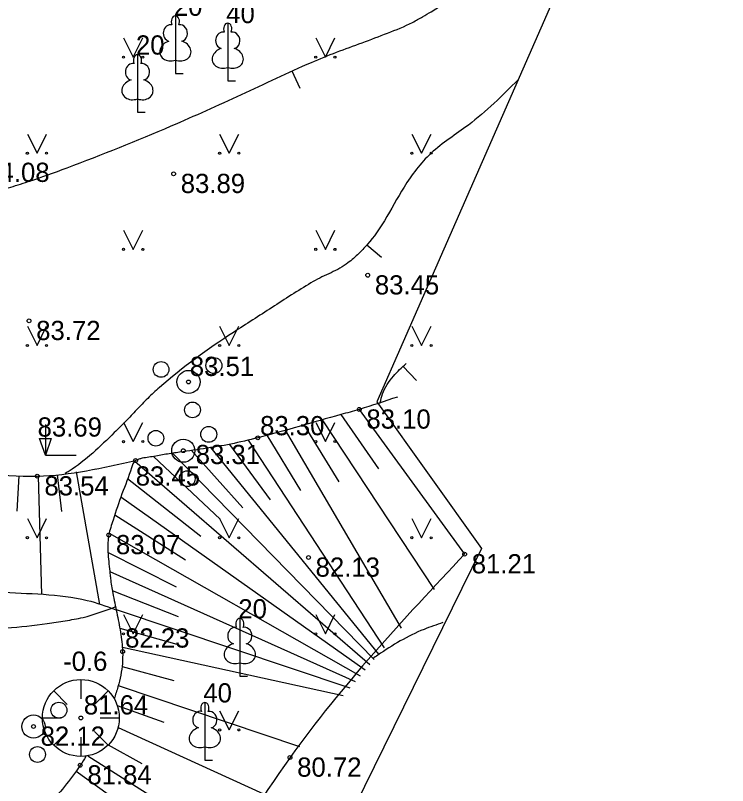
# Model space of a CAD drawing. Extents: x 576692 to 577659, y 273254 to 273799.
# Drawn here: x 577554.44 to 577572.96, y 273358.55 to 273378.59 of the extents above; entities that cross this region are included whole.
import ezdxf

# ---------------------------------------------------------------- set-up
doc = ezdxf.new("R2010")
doc.units = 0
for name, color, linetype in [('APGR_SARK_####_####_#', 7, 'Continuous'), ('CELI_TAKA_####_####_#', 7, 'Continuous'), ('GAZE_ELEM_####_####_#', 7, 'Continuous'), ('GEOD_ELEM_####_TKST_#', 7, 'Continuous'), ('GEOD_SITP_####_TKST_#', 7, 'Continuous'), ('HIDT_REZV_####_TKST_#', 7, 'Continuous'), ('LKAN_ELEM_PAST_TKST_#', 7, 'Continuous'), ('LKAN_VADP_PAST_####_#', 7, 'Continuous'), ('RELJ_ELEM_####_####_#', 7, 'Continuous'), ('SAKT_ELEM_####_####_#', 7, 'Continuous')]:
    doc.layers.add(name, color=color, linetype=linetype)

msp = doc.modelspace()

# ---------------------------------------------------------------- linework, layer by layer
at = {"layer": 'CELI_TAKA_####_####_#'}
msp.add_lwpolyline([(577600.316, 273457.536), (577582.857, 273411.886), (577563.839, 273368.538), (577566.562, 273364.718), (577549.809, 273330.664), (577542.026, 273316.827), (577531.9, 273318.477), (577518.827, 273308.06), (577506.987, 273310.355), (577491.731, 273322.549), (577476.131, 273318.008), (577456.124, 273316.473), (577442.567, 273287.391)], dxfattribs=at)
at = {"layer": 'GAZE_ELEM_####_####_#'}
for p, q in [((577563.382, 273368.337), (577566.122, 273364.573)), ((577562.9, 273368.202), (577563.886, 273366.793)), ((577561.937, 273367.933), (577562.854, 273366.453)), ((577562.419, 273368.068), (577565.329, 273363.649)), ((577561.456, 273367.799), (577564.468, 273362.647)), ((577560.492, 273367.534), (577564.026, 273362.132)), ((577560.974, 273367.664), (577561.855, 273366.225)), ((577559.51, 273367.343), (577563.886, 273361.968)), ((577560.003, 273367.428), (577561.062, 273365.985)), ((577558.521, 273367.195), (577563.767, 273361.83)), ((577559.016, 273367.268), (577560.354, 273365.774)), ((577557.493, 273366.996), (577557.493, 273366.996)), ((577557.546, 273366.995), (577563.66, 273361.705)), ((577558.028, 273367.114), (577559.76, 273365.485)), ((577556.511, 273366.804), (577556.511, 273366.804)), ((577557.001, 273366.904), (577557.001, 273366.904)), ((577554.528, 273366.611), (577554.472, 273365.694)), ((577555.027, 273366.601), (577555.115, 273363.521)), ((577555.526, 273366.637), (577555.639, 273365.685)), ((577556.02, 273366.71), (577556.627, 273363.267)), ((577557.353, 273366.538), (577559.263, 273365.038)), ((577557.184, 273366.067), (577563.536, 273361.561)), ((577557.023, 273365.594), (577558.859, 273364.424)), ((577556.877, 273365.116), (577563.404, 273361.407)), ((577558.63, 273363.716), (577556.846, 273364.619)), ((577556.893, 273364.121), (577563.275, 273361.257)), ((577556.959, 273363.625), (577558.673, 273362.954)), ((577557.056, 273363.135), (577563.134, 273361.093)), ((577557.153, 273362.645), (577558.64, 273362.23)), ((577557.22, 273362.149), (577562.963, 273360.893)), ((577557.212, 273361.65), (577558.559, 273361.287)), ((577557.115, 273361.16), (577561.825, 273359.568)), ((577557.086, 273360.64), (577558.297, 273360.201)), ((577557.111, 273360.068), (577560.895, 273358.341)), ((577556.853, 273359.609), (577557.73, 273359.13)), ((577556.321, 273359.328), (577560.103, 273356.941)), ((577556.017, 273358.93), (577557.132, 273358.13))]:
    msp.add_line(p, q, dxfattribs=at)
for points in [[(577556.274, 273359.307), (577556.124, 273359.082), (577555.713, 273358.527), (577555.271, 273358.028), (577554.768, 273357.574), (577554.485, 273357.361), (577554.334, 273357.257), (577554.176, 273357.155), (577554.073, 273357.1), (577553.967, 273357.063), (577553.861, 273357.047), (577553.757, 273357.054), (577553.172, 273357.221), (577552.593, 273357.48), (577552.308, 273357.66), (577552.157, 273357.847), (577552.118, 273357.98), (577552.083, 273358.112), (577552.023, 273358.376), (577551.94, 273358.907), (577551.893, 273359.44), (577551.866, 273359.976), (577551.783, 273362.009), (577551.767, 273363.023), (577551.775, 273363.531), (577551.794, 273364.038), (577551.842, 273364.628), (577551.911, 273365.218), (577551.985, 273365.808), (577552.044, 273366.397), (577552.052, 273366.952), (577552.016, 273367.194), (577551.954, 273367.432), (577551.775, 273367.893), (577551.652, 273368.142), (577551.524, 273368.386), (577551.279, 273368.88), (577550.489, 273370.674), (577550.237, 273371.247), (577549.35, 273372.831), (577548.462, 273374.158)], [(577564.374, 273368.659), (577563.382, 273368.337), (577562.9, 273368.202), (577560.742, 273367.599), (577560.042, 273367.436), (577559.333, 273367.315), (577558.62, 273367.21), (577558.264, 273367.155), (577557.909, 273367.093), (577557.735, 273367.066), (577557.649, 273367.044), (577557.607, 273367.029), (577557.565, 273367.008), (577557.494, 273366.924), (577557.456, 273366.817), (577557.21, 273366.14), (577556.978, 273365.457), (577556.868, 273365.071), (577556.851, 273364.947), (577556.843, 273364.821), (577556.849, 273364.569), (577556.898, 273364.066), (577556.912, 273363.939), (577556.971, 273363.558), (577557.074, 273363.051), (577557.171, 273362.544), (577557.206, 273362.29), (577557.227, 273362.037), (577557.177, 273361.425), (577557.104, 273361.12), (577557.009, 273360.815)], [(577552.052, 273366.952), (577555.007, 273366.6), (577557.565, 273367.008)]]:
    msp.add_spline(points, degree=3, dxfattribs=at)
at = {"layer": 'GEOD_ELEM_####_TKST_#'}
msp.add_line((577561.847, 273376.684), (577561.641, 273377.139), dxfattribs=at)
msp.add_spline([(577552.135, 273373.738), (577552.569, 273373.777), (577553.728, 273373.95), (577554.251, 273374.099), (577554.767, 273374.261), (577555.784, 273374.622), (577558.491, 273375.711), (577559.408, 273376.113), (577560.319, 273376.53), (577561.227, 273376.95), (577562.139, 273377.363), (577562.794, 273377.63), (577563.457, 273377.875), (577564.119, 273378.125), (577564.769, 273378.405), (577565.029, 273378.55), (577565.252, 273378.682), (577565.57, 273378.894), (577565.767, 273379.042), (577565.833, 273379.094), (577565.934, 273379.188), (577566.124, 273379.412), (577566.454, 273379.912), (577566.84, 273380.678), (577567.333, 273381.728), (577567.755, 273382.508)], degree=3, dxfattribs=at)
at = {"layer": 'GEOD_SITP_####_TKST_#'}
for p, q in [((577563.959, 273372.285), (577563.577, 273372.608)), ((577564.873, 273369.093), (577564.523, 273369.45))]:
    msp.add_line(p, q, dxfattribs=at)
for points in [[(577567.517, 273376.913), (577566.219, 273375.733), (577565.25, 273375), (577564.547, 273374.12), (577564.038, 273373.246), (577563.599, 273372.634), (577563.338, 273372.361), (577563.045, 273372.118), (577562.823, 273371.98), (577562.589, 273371.865), (577562.353, 273371.754), (577562.126, 273371.628), (577561.114, 273370.989), (577560.107, 273370.339), (577558.185, 273368.906), (577557.88, 273368.624), (577557.591, 273368.327), (577557.305, 273368.027), (577557.011, 273367.734), (577555.838, 273366.733), (577555.736, 273366.67)], [(577563.928, 273368.515), (577563.986, 273368.74), (577564.269, 273369.202), (577564.604, 273369.53)], [(577551.773, 273362.801), (577551.816, 273362.78), (577552.477, 273362.62), (577553.145, 273362.622), (577553.675, 273362.634), (577554.206, 273362.658), (577555.266, 273362.767), (577555.734, 273362.84), (577556.198, 273362.928), (577557.034, 273363.201)], [(577565.554, 273362.793), (577565.066, 273362.616), (577563.867, 273361.947), (577563.731, 273361.852)]]:
    msp.add_spline(points, degree=3, dxfattribs=at)
at = {"layer": 'LKAN_ELEM_PAST_TKST_#'}
for p, q in [((577557.25, 273378), (577557.5, 273377.5)), ((577557.5, 273377.5), (577557.75, 273378)), ((577562.25, 273378), (577562.5, 273377.5)), ((577562.5, 273377.5), (577562.75, 273378)), ((577558.599, 273377.421), (577558.599, 273377.074)), ((577559.961, 273377.231), (577559.961, 273376.884)), ((577558.599, 273377.074), (577558.799, 273377.074)), ((577559.961, 273376.884), (577560.161, 273376.884)), ((577557.613, 273376.413), (577557.613, 273376.066)), ((577557.613, 273376.066), (577557.813, 273376.066)), ((577554.75, 273375.5), (577555, 273375)), ((577555, 273375), (577555.25, 273375.5)), ((577559.75, 273375.5), (577560, 273375)), ((577560, 273375), (577560.25, 273375.5)), ((577564.75, 273375.5), (577565, 273375)), ((577565, 273375), (577565.25, 273375.5)), ((577557.25, 273373), (577557.5, 273372.5)), ((577557.5, 273372.5), (577557.75, 273373)), ((577562.25, 273373), (577562.5, 273372.5)), ((577562.5, 273372.5), (577562.75, 273373)), ((577554.75, 273370.5), (577555, 273370)), ((577555, 273370), (577555.25, 273370.5)), ((577559.75, 273370.5), (577560, 273370)), ((577560, 273370), (577560.25, 273370.5)), ((577564.75, 273370.5), (577565, 273370)), ((577565, 273370), (577565.25, 273370.5)), ((577555.217, 273367.948), (577555.217, 273367.148)), ((577557.25, 273368), (577557.5, 273367.5)), ((577557.5, 273367.5), (577557.75, 273368)), ((577562.25, 273368), (577562.5, 273367.5)), ((577562.5, 273367.5), (577562.75, 273368)), ((577555.217, 273367.148), (577556.017, 273367.148)), ((577554.75, 273365.5), (577555, 273365)), ((577555, 273365), (577555.25, 273365.5)), ((577559.75, 273365.5), (577560, 273365)), ((577560, 273365), (577560.25, 273365.5)), ((577564.75, 273365.5), (577565, 273365)), ((577565, 273365), (577565.25, 273365.5)), ((577557.25, 273363), (577557.5, 273362.5)), ((577557.5, 273362.5), (577557.75, 273363)), ((577562.25, 273363), (577562.5, 273362.5)), ((577562.5, 273362.5), (577562.75, 273363)), ((577560.275, 273361.748), (577560.275, 273361.401)), ((577560.275, 273361.401), (577560.475, 273361.401)), ((577559.75, 273360.5), (577560, 273360)), ((577560, 273360), (577560.25, 273360.5)), ((577559.365, 273359.562), (577559.365, 273359.215)), ((577559.365, 273359.215), (577559.565, 273359.215))]:
    msp.add_line(p, q, dxfattribs=at)
for points in [[(577558.599, 273378.574), (577558.599, 273377.421)], [(577559.961, 273378.384), (577559.961, 273377.231)], [(577558.689, 273378.342), (577558.688, 273378.343)], [(577560.051, 273378.152), (577560.05, 273378.153)], [(577557.613, 273377.566), (577557.613, 273376.413)], [(577557.703, 273377.334), (577557.702, 273377.335)], [(577560.275, 273362.901), (577560.275, 273361.748)], [(577560.365, 273362.669), (577560.364, 273362.67)], [(577559.365, 273360.715), (577559.365, 273359.562)], [(577559.455, 273360.483), (577559.454, 273360.484)]]:
    msp.add_lwpolyline(points, dxfattribs=at)
for centre, radius in [((577557.25, 273377.5), 0.028), ((577557.75, 273377.5), 0.0263), ((577562.25, 273377.5), 0.028), ((577562.75, 273377.5), 0.0263), ((577554.75, 273375), 0.028), ((577555.25, 273375), 0.0263), ((577559.75, 273375), 0.028), ((577560.25, 273375), 0.0263), ((577564.75, 273375), 0.028), ((577565.25, 273375), 0.0263), ((577557.25, 273372.5), 0.028), ((577557.75, 273372.5), 0.0263), ((577562.25, 273372.5), 0.028), ((577562.75, 273372.5), 0.0263), ((577554.75, 273370), 0.028), ((577555.25, 273370), 0.0263), ((577559.75, 273370), 0.028), ((577560.25, 273370), 0.0263), ((577564.75, 273370), 0.028), ((577565.25, 273370), 0.0263), ((577558.227, 273369.376), 0.204), ((577559.602, 273369.477), 0.207), ((577558.941, 273369.052), 0.301), ((577559.044, 273368.324), 0.205), ((577558.091, 273367.587), 0.204), ((577559.466, 273367.688), 0.207), ((577558.805, 273367.263), 0.301), ((577557.25, 273367.5), 0.028), ((577557.75, 273367.5), 0.0263), ((577562.25, 273367.5), 0.028), ((577562.75, 273367.5), 0.0263), ((577558.908, 273366.535), 0.205), ((577554.75, 273365), 0.028), ((577555.25, 273365), 0.0263), ((577559.75, 273365), 0.028), ((577560.25, 273365), 0.0263), ((577564.75, 273365), 0.028), ((577565.25, 273365), 0.0263), ((577557.25, 273362.5), 0.028), ((577557.75, 273362.5), 0.0263), ((577562.25, 273362.5), 0.028), ((577562.75, 273362.5), 0.0263), ((577555.57, 273360.514), 0.207), ((577554.909, 273360.089), 0.301), ((577559.75, 273360), 0.028), ((577560.25, 273360), 0.0263), ((577555.012, 273359.361), 0.205)]:
    msp.add_circle(centre, radius, dxfattribs=at)
for centre, major_axis, ratio, start_param, end_param in [((577558.599, 273378.424), (0, -0.15), 0.707107, 3.14537, 5.287485), ((577558.599, 273378.424), (0, -0.15), 0.707107, 0.995701, 3.137816), ((577558.471, 273378.129), (-0.039, -0.212), 0.861323, 3.141593, 6.283185), ((577558.727, 273378.129), (0.039, -0.212), 0.861323, 0, 3.141593), ((577559.961, 273378.234), (0, -0.15), 0.707107, 3.14537, 5.287485), ((577559.961, 273378.234), (0, -0.15), 0.707107, 0.995701, 3.137816), ((577559.833, 273377.939), (-0.039, -0.212), 0.861323, 3.141593, 6.283185), ((577560.089, 273377.939), (0.039, -0.212), 0.861323, 0, 3.141593), ((577558.509, 273377.667), (0.307, 0.095), 0.814445, 1.570796, 4.752015), ((577558.689, 273377.667), (-0.307, 0.095), 0.814445, 1.531171, 4.712389), ((577557.613, 273377.416), (0, -0.15), 0.707107, 3.14537, 5.287485), ((577557.613, 273377.416), (0, -0.15), 0.707107, 0.995701, 3.137816), ((577559.871, 273377.477), (0.307, 0.095), 0.814445, 1.570796, 4.752015), ((577560.051, 273377.477), (-0.307, 0.095), 0.814445, 1.531171, 4.712389), ((577557.485, 273377.121), (-0.039, -0.212), 0.861323, 3.141593, 6.283185), ((577557.741, 273377.121), (0.039, -0.212), 0.861323, 0, 3.141593), ((577557.523, 273376.659), (0.307, 0.095), 0.814445, 1.570796, 4.752015), ((577557.703, 273376.659), (-0.307, 0.095), 0.814445, 1.531171, 4.712389), ((577560.275, 273362.751), (0, -0.15), 0.707107, 3.14537, 5.287485), ((577560.275, 273362.751), (0, -0.15), 0.707107, 0.995701, 3.137816), ((577560.147, 273362.456), (-0.039, -0.212), 0.861323, 3.141593, 6.283185), ((577560.403, 273362.456), (0.039, -0.212), 0.861323, 0, 3.141593), ((577560.185, 273361.994), (0.307, 0.095), 0.814445, 1.570796, 4.752015), ((577560.365, 273361.994), (-0.307, 0.095), 0.814445, 1.531171, 4.712389), ((577559.365, 273360.565), (0, -0.15), 0.707107, 3.14537, 5.287485), ((577559.365, 273360.565), (0, -0.15), 0.707107, 0.995701, 3.137816), ((577559.237, 273360.27), (-0.039, -0.212), 0.861323, 3.141593, 6.283185), ((577559.493, 273360.27), (0.039, -0.212), 0.861323, 0, 3.141593), ((577559.275, 273359.808), (0.307, 0.095), 0.814445, 1.570796, 4.752015), ((577559.455, 273359.808), (-0.307, 0.095), 0.814445, 1.531171, 4.712389)]:
    msp.add_ellipse(centre, major_axis=major_axis, ratio=ratio, start_param=start_param, end_param=end_param, dxfattribs=at)
at = {"layer": 'RELJ_ELEM_####_####_#'}
for p, q in [((577556.141, 273361.312), (577556.141, 273360.812)), ((577555.434, 273361.019), (577555.788, 273360.665)), ((577556.495, 273360.665), (577556.848, 273361.019)), ((577555.141, 273360.312), (577555.641, 273360.312)), ((577556.641, 273360.312), (577557.141, 273360.312)), ((577555.434, 273359.605), (577555.788, 273359.958)), ((577556.495, 273359.958), (577556.848, 273359.605)), ((577556.141, 273359.812), (577556.141, 273359.312))]:
    msp.add_line(p, q, dxfattribs=at)
msp.add_lwpolyline([(577555.067, 273367.581), (577555.367, 273367.581), (577555.217, 273367.148)], close=True, dxfattribs=at)
for centre, radius in [((577558.553, 273374.465), 0.05), ((577563.602, 273371.827), 0.05), ((577554.793, 273370.641), 0.05), ((577558.941, 273369.052), 0.05), ((577563.382, 273368.337), 0.05), ((577560.742, 273367.599), 0.05), ((577558.805, 273367.263), 0.05), ((577557.565, 273367.008), 0.05), ((577555.007, 273366.6), 0.05), ((577556.868, 273365.071), 0.05), ((577562.06, 273364.486), 0.05), ((577566.122, 273364.573), 0.05), ((577557.227, 273362.037), 0.05), ((577556.141, 273360.312), 1), ((577556.141, 273360.312), 0.05), ((577554.909, 273360.089), 0.05), ((577561.581, 273359.284), 0.05), ((577556.124, 273359.082), 0.05)]:
    msp.add_circle(centre, radius, dxfattribs=at)
at = {"layer": 'SAKT_ELEM_####_####_#'}
for points in [[(577566.122, 273364.573), (577561.581, 273359.284), (577559.461, 273355.795), (577557.79, 273353.035), (577555.581, 273351.547), (577552.575, 273351.059), (577550.473, 273352.838), (577549.839, 273356.809), (577549.009, 273361.77), (577547.351, 273367.038), (577547.543, 273370.779), (577548.131, 273373.034), (577548.462, 273374.158)], [(577551.794, 273364.038), (577554.004, 273363.603), (577556.307, 273363.37), (577557.03, 273363.137)]]:
    msp.add_spline(points, degree=3, dxfattribs=at)

# ---------------------------------------------------------------- texts
at = {"layer": 'APGR_SARK_####_####_#'}
for s, p in [(' 20', (577558.374, 273378.574)), (' 40', (577559.736, 273378.384)), (' 20', (577557.388, 273377.566)), (' 20', (577560.05, 273362.901)), (' 40', (577559.14, 273360.715))]:
    msp.add_text(s, height=0.5, dxfattribs=at).set_placement(p)
at = {"layer": 'HIDT_REZV_####_TKST_#'}
for s, p in [(' 84.08', (577553.469, 273374.254)), (' 83.89', (577558.553, 273373.965)), (' 83.45', (577563.602, 273371.327)), (' 83.72', (577554.793, 273370.141)), (' 83.51', (577558.789, 273369.207)), (' 83.10', (577563.382, 273367.837)), (' 83.69', (577554.83, 273367.63)), (' 83.30', (577560.617, 273367.665)), (' 83.31', (577558.942, 273366.915)), (' 83.45', (577557.382, 273366.356)), (' 83.54', (577555.007, 273366.1)), (' 83.07', (577556.868, 273364.571)), (' 81.21', (577566.122, 273364.073)), (' 82.13', (577562.06, 273363.986)), (' 82.23', (577557.106, 273362.142)), (' 81.64', (577556.032, 273360.403)), (' 82.12', (577554.909, 273359.589)), (' 80.72', (577561.581, 273358.784)), (' 81.84', (577556.124, 273358.582))]:
    msp.add_text(s, height=0.5, dxfattribs=at).set_placement(p)
at = {"layer": 'LKAN_VADP_PAST_####_#'}
msp.add_text('-0.6', height=0.5, dxfattribs=at).set_placement((577555.679, 273361.537))

doc.saveas('drawing.dxf')
